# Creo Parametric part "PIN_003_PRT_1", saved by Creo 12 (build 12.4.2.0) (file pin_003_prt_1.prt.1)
Units: Custom; MM, KILOGRAM, SECS

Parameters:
  PTC_WM_ITERATION = "0"
  PTC_WM_VERSION = "-.0"
  PTC_WM_LIFECYCLE_STATE = "In Work"
  PTC_WM_LIFECYCLE = "MO_CADDocument"
  PTC_WM_CREATED_BY = "Maximilian Roepper (Z0017RMS: MO)"
  PTC_WM_CREATED_ON = "18-Sep-26 11:36:42 AM"
  PTC_WM_MODIFIED_BY = "Maximilian Roepper (Z0017RMS: MO)"
  PTC_WM_MODIFIED_ON = "18-Sep-26 11:36:46 AM"
  PDMLINKNUMBER = "PDM000071455261"
  PTC_WM_NAME = "pin_003_prt_1.prt"
  PTC_WM_NUMBER = "PDM000071455261"

Other parameters: WEIGHT, WEIGHT_FACTOR, WEIGHT_ADD, _MASS_TEMP, _DIFF_TEMP, MC_ERRORS, SUPPLIER

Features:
  1. coordinate system
  2. datum plane "PRT_YZ"
  3. datum plane "PRT_XY"
  4. datum plane "PRT_XZ"
  5. coordinate system
  6. datum axis
  7. datum axis
  8. datum axis
  9. coordinate system
  10. imported feature
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
Other named items: PRT, SIEMENS_MO, DRW_VIEW_ORG, PRT_X, PRT_Y, PRT_Z, CS0, ROUGH_GROB

Layers: 00_STD_CSYS-KSYS, 01_STD_PLANES-EBENEN, 02_STD_AXES-ACHSEN, 03_STD_CSYS-KSYS, 24_IMPORT_FEAT-IMPORT_KE

Surfaces: 9 plane, 1 cylinder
